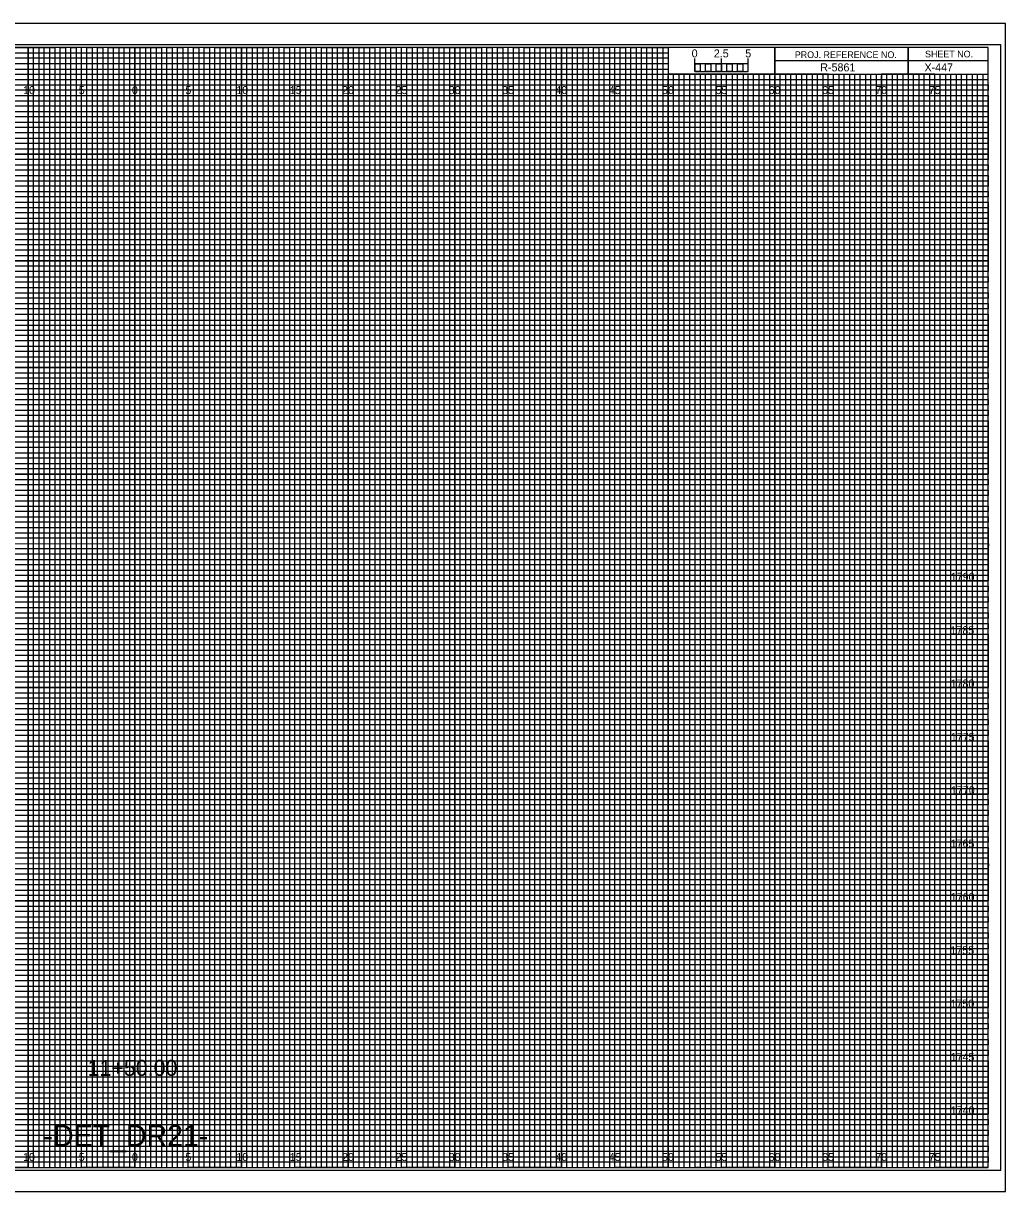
# Model space of a CAD drawing. Extents: x -7 to 162, y -2 to 217.
# Drawn here: x 69.5 to 161.7, y 107.7 to 217.2 of the extents above; entities that cross this region are included whole.
import ezdxf

# ---------------------------------------------------------------- set-up
doc = ezdxf.new("R2010")
doc.units = 0
for name, color, linetype in [('Prop Horizontal Alignment', 7, 'Continuous'), ('Prop XS Alignment Label', 7, 'Continuous'), ('Prop XS Bar Scale Labels', 7, 'Continuous'), ('Prop XS Project Number', 7, 'Continuous'), ('Prop XS Sheet Number', 7, 'Continuous'), ('Raster_Level_0', 7, 'Continuous'), ('Scratch_Level_3', 7, 'Continuous'), ('Sheet Cross Section CELL', 7, 'Continuous'), ('Sheet Cross Section Grid Major CELL', 7, 'Continuous'), ('Sheet Cross Section Grid Middle CELL', 7, 'Continuous'), ('Sheet Cross Section Grid Minor 1 CELL', 7, 'Continuous'), ('Sheet Cross Section Grid Minor 2 CELL', 7, 'Continuous'), ('Sheet Cross Section Scale CELL', 7, 'Continuous'), ('Sheet Cutting Line CELL', 7, 'Continuous'), ('Sheet DOT Grid CELL', 7, 'Continuous'), ('Sheet Plot Border Inside CELL', 7, 'Continuous'), ('Sheet Plot Border Outside CELL', 7, 'Continuous')]:
    doc.layers.add(name, color=color, linetype=linetype)

msp = doc.modelspace()

# ---------------------------------------------------------------- linework, layer by layer
at = {"layer": 'Sheet Cross Section CELL'}
for p, q in [((152.5, 215), (152.5, 212.5)), ((152.5, 212.5), (152.5, 215)), ((160, 213.75), (140, 213.75)), ((140, 213.75), (140, 212.5)), ((140, 212.5), (160, 212.5))]:
    msp.add_line(p, q, dxfattribs=at)
for points in [[(160, 215), (0, 215), (0, 110), (160, 110)], [(140, 215), (130, 215), (130, 212.52), (140, 212.52)], [(160, 215), (140, 215), (140, 212.5), (160, 212.5)]]:
    msp.add_lwpolyline(points, close=True, dxfattribs=at)
at = {"layer": 'Sheet Cross Section Grid Major CELL'}
for p, q in [((75, 215), (70, 215)), ((70, 215), (70, 110)), ((75, 110), (75, 215)), ((85, 215), (80, 215)), ((80, 215), (80, 110)), ((85, 110), (85, 215)), ((95, 215), (90, 215)), ((90, 215), (90, 110)), ((95, 110), (95, 215)), ((105, 215), (100, 215)), ((100, 215), (100, 110)), ((105, 110), (105, 215)), ((115, 215), (110, 215)), ((110, 215), (110, 110)), ((115, 110), (115, 215)), ((125, 215), (120, 215)), ((120, 215), (120, 110)), ((125, 110), (125, 215)), ((130, 215), (130, 110)), ((135, 110), (135, 212.5)), ((145, 212.5), (140, 212.5)), ((140, 212.5), (140, 110)), ((145, 110), (145, 212.5)), ((155, 212.5), (150, 212.5)), ((150, 212.5), (150, 110)), ((155, 110), (155, 212.5)), ((70, 110), (65, 110)), ((80, 110), (75, 110)), ((90, 110), (85, 110)), ((100, 110), (95, 110)), ((110, 110), (105, 110)), ((120, 110), (115, 110)), ((130, 110), (125, 110)), ((140, 110), (135, 110)), ((150, 110), (145, 110)), ((160, 110), (155, 110)), ((160, 110), (160, 110))]:
    msp.add_line(p, q, dxfattribs=at)
for points in [[(0, 210), (160, 210), (160, 205), (0, 205)], [(0, 200), (160, 200), (160, 195), (0, 195)], [(0, 190), (160, 190), (160, 185), (0, 185)], [(0, 180), (160, 180), (160, 175), (0, 175)], [(0, 170), (160, 170), (160, 165), (0, 165)], [(0, 160), (160, 160), (160, 155), (0, 155)], [(0, 150), (160, 150), (160, 145), (0, 145)], [(0, 140), (160, 140), (160, 135), (0, 135)], [(0, 130), (160, 130), (160, 125), (0, 125)], [(0, 120), (160, 120), (160, 115), (0, 115)]]:
    msp.add_lwpolyline(points, dxfattribs=at)
at = {"layer": 'Sheet Cross Section Grid Middle CELL'}
for points in [[(67.5, 215), (72.5, 215), (72.5, 110), (77.5, 110), (77.5, 215), (82.5, 215), (82.5, 110), (87.5, 110), (87.5, 215), (92.5, 215), (92.5, 110), (97.5, 110), (97.5, 215), (102.5, 215), (102.5, 110), (107.5, 110), (107.5, 215), (112.5, 215), (112.5, 110), (117.5, 110), (117.5, 215), (122.5, 215), (122.5, 110), (127.5, 110), (127.5, 215), (129.97, 215), (130, 215), (130, 212.5), (132.5, 212.5), (132.5, 110), (137.5, 110), (137.5, 212.5), (142.5, 212.5), (142.5, 110), (147.5, 110), (147.5, 212.5), (152.5, 212.5), (152.5, 110), (157.5, 110), (157.5, 212.5)], [(0, 212.5), (137.5, 212.5)], [(0, 202.5), (160, 202.5), (160, 207.5), (0, 207.5)], [(0, 192.5), (160, 192.5), (160, 197.5), (0, 197.5)], [(0, 182.5), (160, 182.5), (160, 187.5), (0, 187.5)], [(0, 172.5), (160, 172.5), (160, 177.5), (0, 177.5)], [(0, 162.5), (160, 162.5), (160, 167.5), (0, 167.5)], [(0, 152.5), (160, 152.5), (160, 157.5), (0, 157.5)], [(0, 142.5), (160, 142.5), (160, 147.5), (0, 147.5)], [(0, 132.5), (160, 132.5), (160, 137.5), (0, 137.5)], [(0, 122.5), (160, 122.5), (160, 127.5), (0, 127.5)], [(0, 112.5), (160, 112.5), (160, 117.5), (0, 117.5)]]:
    msp.add_lwpolyline(points, dxfattribs=at)
at = {"layer": 'Sheet Cross Section Grid Minor 1 CELL'}
for p, q in [((0, 214.5), (130, 214.5)), ((130, 213.99), (0, 213.99)), ((130, 214.5), (130, 213.99)), ((0, 213.5), (130, 213.5)), ((130, 212.94), (0, 212.94)), ((130, 213.5), (130, 212.94)), ((0, 212), (160, 212))]:
    msp.add_line(p, q, dxfattribs=at)
for points in [[(0, 211.5), (135, 211.5), (160, 211.5), (160, 211), (0, 211)], [(0, 210.5), (160, 210.5), (160, 209.5), (0, 209.5)], [(0, 209), (160, 209), (160, 208.5), (0, 208.49)], [(0, 208), (160, 208), (160, 207), (0, 207)], [(0, 206.5), (160, 206.5), (160, 206), (0, 206)], [(0, 205.5), (160, 205.5), (160, 204.5), (0, 204.5)], [(0, 204), (160, 204), (160, 203.5), (0, 203.5)], [(0, 203), (160, 203), (160, 202), (0, 202)], [(0, 201.5), (160, 201.5), (160, 201), (0, 201)], [(0, 200.5), (160, 200.5), (160, 199.5), (0, 199.5)], [(0, 199), (160, 199), (160, 198.5), (0, 198.5)], [(0, 198), (160, 198), (160, 196.97), (160, 196.5), (160, 196), (0, 196)], [(0, 197), (160, 197), (160, 196.5), (0, 196.5)], [(0, 195.5), (160, 195.5), (160, 194.5), (0, 194.52)], [(0, 194.52), (160, 194.5), (160, 194), (0, 194)], [(0, 193.5), (160, 193.5), (160, 193), (0, 193)], [(0, 192), (160, 192), (160, 191.5), (0, 191.5)], [(0, 191), (160, 191), (160, 190.5), (0, 190.5)], [(-0.04, 189.44), (160, 189.44), (160, 188.94), (-0.04, 188.94)], [(0, 188.5), (160, 188.5), (160, 188), (0, 188)], [(0, 187), (160, 187), (160, 186.5), (0, 186.5)], [(0, 186), (160, 186), (160, 185.5), (0, 185.5)], [(0, 184.5), (160, 184.5), (160, 184), (0, 184)], [(0, 183.5), (160, 183.5), (160, 183), (0, 183)], [(0, 182), (160, 182), (160, 181.5), (0, 181.5)], [(0, 181), (160, 181), (160, 180.5), (0, 180.5)], [(0, 179.5), (160, 179.5), (160, 178.99), (0, 179)], [(0, 178.5), (160, 178.5), (160, 178), (0, 178)], [(0, 177), (160, 177), (160, 176.5), (0, 176.5)], [(0, 176), (160, 176), (160, 175.5), (0, 175.5)], [(0, 174.5), (160, 174.5), (160, 174), (0, 174)], [(0, 173.5), (160, 173.5), (160, 173), (0, 173)], [(0, 172), (160, 172), (160, 171.5), (0, 171.5)], [(0, 171), (160, 171), (160, 170.5), (0, 170.5)], [(0, 169.5), (160, 169.5), (160, 169), (0, 169)], [(0, 168.5), (160.03, 168.46), (160, 168), (0, 168)], [(0, 167), (160, 167), (160, 166.5), (0, 166.5)], [(0, 166), (160, 166), (160, 165.5), (0, 165.5)], [(0, 164.5), (160, 164.5), (160, 164), (0, 164)], [(0, 163.5), (160, 163.5), (160, 163), (0, 163)], [(0, 162), (160, 162), (160, 161.5), (0, 161.5)], [(0, 161), (160, 161), (160, 160.5), (0, 160.5)], [(0, 159.5), (160, 159.5), (160, 159), (0, 159)], [(0, 158.5), (160, 158.5), (160, 158), (0, 158)], [(0, 157), (160, 157), (160, 156.5), (0, 156.5)], [(0, 156), (160, 156), (160, 155.5), (0, 155.5)], [(0, 154.5), (160, 154.5), (160, 154), (0, 154)], [(0, 153.5), (160, 153.5), (160, 153), (0, 153)], [(0, 152), (160, 152), (160, 151.5), (0, 151.5)], [(0, 151), (160, 151), (160, 150.5), (0, 150.5)], [(0, 149.5), (160, 149.5), (160, 148.99), (0, 149)], [(0, 148.5), (160, 148.5), (160, 148), (0, 148)], [(0, 147), (160, 147), (160, 146.5), (0, 146.5)], [(0, 146), (160, 146), (160, 145.5), (0, 145.5)], [(0, 144.5), (160, 144.5), (160, 144), (0, 144)], [(0, 143.5), (160, 143.5), (160, 143), (0, 143)], [(0, 142), (160, 142), (160, 141.5), (0, 141.5)], [(0, 141), (160, 141), (160, 140.5), (0, 140.5)], [(0, 139.5), (160, 139.5), (160, 139), (0, 139)], [(0, 138.5), (160.03, 138.46), (160, 138), (0, 138)], [(0, 137), (160, 137), (160, 136.5), (0, 136.5)], [(0, 136), (160, 136), (160, 135.5), (0, 135.5)], [(0, 134.5), (160, 134.5), (160, 134), (0, 134)], [(0, 133.5), (160, 133.5), (160, 133), (0, 133)], [(0, 132), (160, 132), (160, 131.5), (0, 131.5)], [(0, 131), (160, 131), (160, 130.5), (0, 130.5)], [(0, 129.5), (160, 129.5), (160, 129), (0, 129)], [(0, 128.5), (160, 128.5), (160, 128), (0, 128)], [(0, 127), (160, 127), (160, 126.5), (0, 126.5)], [(0, 126), (160, 126), (160, 125.5), (0, 125.5)], [(0, 124.5), (160, 124.5), (160, 124), (0, 124)], [(0, 123.5), (160, 123.5), (160, 123), (0, 123)], [(0, 122), (160, 122), (160, 121.5), (0, 121.5)], [(0, 121), (160, 121), (160, 120.5), (0, 120.5)], [(0, 119.5), (160, 119.5), (160, 119), (0, 119)], [(0, 118.5), (160, 118.5), (160, 118), (0, 118)], [(0, 117), (160, 117), (160, 116.5), (0, 116.5)], [(0, 116), (160, 116), (160, 115.5), (0, 115.5)], [(0, 114.5), (160, 114.5), (160, 114), (0, 114)], [(0, 113.5), (160, 113.5), (160, 113), (0, 113)], [(0, 112), (160, 112), (160, 111.5), (0, 111.5)], [(0, 111), (160, 111), (160, 110.5), (0, 110.5)]]:
    msp.add_lwpolyline(points, dxfattribs=at)
at = {"layer": 'Sheet Cross Section Grid Minor 2 CELL'}
for p, q in [((133.5, 212.5), (133, 212.5)), ((133, 212.5), (133, 110)), ((133.5, 110), (133.5, 212.5)), ((134.5, 212.5), (134, 212.5)), ((134, 212.5), (134, 110)), ((134.5, 110), (134.5, 212.5)), ((133, 110), (132.5, 110)), ((134, 110), (133.5, 110))]:
    msp.add_line(p, q, dxfattribs=at)
for points in [[(70, 110), (70.5, 110), (70.5, 215), (71, 215), (71, 110)], [(71, 110), (71.5, 110), (71.5, 215), (72, 215), (72, 110)], [(72.5, 110), (73, 110), (73, 215), (73.5, 215), (73.5, 110)], [(73.5, 110), (74, 110), (74, 215), (74.5, 215), (74.5, 110)], [(75, 110), (75.5, 110), (75.5, 215), (76, 215), (76, 110)], [(76, 110), (76.5, 110), (76.5, 215), (77, 215), (77, 110)], [(77.5, 110), (78, 110), (78, 215), (78.5, 215), (78.5, 110)], [(78.5, 110), (79, 110), (79, 215), (79.5, 215), (79.5, 110)], [(80, 110), (80.5, 110), (80.5, 215), (81, 215), (81, 110)], [(81, 110), (81.5, 110), (81.5, 215), (82, 215), (82, 110)], [(82.5, 110), (83, 110), (83, 215), (83.5, 215), (83.5, 110)], [(83.5, 110), (84, 110), (84, 215), (84.5, 215), (84.5, 110)], [(85, 110), (85.5, 110), (85.5, 215), (86, 215), (86, 110)], [(86, 110), (86.5, 110), (86.5, 215), (87, 215), (87, 110)], [(87.5, 110), (88, 110), (88, 215), (88.5, 215), (88.5, 110)], [(88.5, 110), (89, 110), (89, 215), (89.5, 215), (89.5, 110)], [(90, 110), (90.5, 110), (90.5, 215), (91, 215), (91, 110)], [(91, 110), (91.5, 110), (91.5, 215), (92, 215), (92, 110)], [(92.5, 110), (93, 110), (93, 215), (93.5, 215), (93.5, 110)], [(93.5, 110), (94, 110), (94, 215), (94.5, 215), (94.5, 110)], [(95, 110), (95.5, 110), (95.5, 215), (96, 215), (96, 110)], [(96, 110), (96.5, 110), (96.5, 215), (97, 215), (97, 110)], [(97.5, 110), (98, 110), (98, 215), (98.5, 215), (98.5, 110)], [(98.5, 110), (99, 110), (99, 215), (99.5, 215), (99.5, 110)], [(100, 110), (100.5, 110), (100.5, 215), (101, 215), (101, 110)], [(101, 110), (101.5, 110), (101.5, 215), (102, 215), (102, 110)], [(102.5, 110), (103, 110), (103, 215), (103.5, 215), (103.5, 110)], [(103.5, 110), (104, 110), (104, 215), (104.5, 215), (104.5, 110)], [(105, 110), (105.5, 110), (105.5, 215), (106, 215), (106, 110)], [(106, 110), (106.5, 110), (106.5, 215), (107, 215), (107, 110)], [(107.5, 110), (108, 110), (108, 215), (108.5, 215), (108.5, 110)], [(108.5, 110), (109, 110), (109, 215), (109.5, 215), (109.5, 110)], [(110, 110), (110.5, 110), (110.5, 215), (111, 215), (111, 110)], [(111, 110), (111.5, 110), (111.5, 215), (112, 215), (112, 110)], [(112.5, 110), (113, 110), (113, 215), (113.5, 215), (113.5, 110)], [(113.5, 110), (114, 110), (114, 215), (114.5, 215), (114.5, 110)], [(115, 110), (115.5, 110), (115.5, 215), (116, 215), (116, 110)], [(116, 110), (116.5, 110), (116.5, 215), (117, 215), (117, 110)], [(117.5, 110), (118, 110), (118, 215), (118.5, 215), (118.5, 110)], [(118.5, 110), (119, 110), (119, 215), (119.5, 215), (119.5, 110)], [(120, 110), (120.5, 110), (120.5, 215), (121, 215), (121, 110)], [(121, 110), (121.5, 110), (121.5, 215), (122, 215), (122, 110)], [(122.5, 110), (123, 110), (123, 215), (123.5, 215), (123.5, 110)], [(123.5, 110), (124, 110), (124, 215), (124.5, 215), (124.5, 110)], [(125, 110), (125.5, 110), (125.5, 215), (126, 215), (126, 110)], [(126, 110), (126.5, 110), (126.5, 215), (127, 215), (127, 110)], [(127.5, 110), (128, 110), (128, 215), (128.5, 215), (128.5, 110)], [(128.5, 110), (129, 110), (129, 215), (129.5, 215), (129.5, 110)], [(130, 110), (130.5, 110), (130.5, 212.5), (131.01, 212.5), (131.01, 110)], [(131, 110), (131.5, 110), (131.5, 212.5), (132, 212.5), (132, 110)], [(135, 110), (135.49, 110), (135.49, 212.5), (136, 212.5), (136, 110)], [(136, 110), (136.5, 110), (136.5, 212.5), (137.03, 212.5), (137.03, 110)], [(137.5, 110), (138, 110), (138, 212.5), (138.5, 212.5), (138.5, 110)], [(138.5, 110), (139, 110), (139, 212.5), (139.5, 212.5), (139.5, 110)], [(140, 110), (140.5, 110), (140.5, 212.5), (141, 212.5), (141, 110)], [(141, 110), (141.5, 110), (141.5, 212.5), (142, 212.5), (142, 110)], [(142.5, 110), (143, 110), (143, 212.5), (143.5, 212.5), (143.5, 110)], [(143.5, 110), (144, 110), (144, 212.5), (144.5, 212.5), (144.5, 110)], [(145, 110), (145.5, 110), (145.5, 212.5), (146, 212.5), (146, 110)], [(146, 110), (146.5, 110), (146.5, 212.5), (147, 212.5), (147, 110)], [(147.5, 110), (148, 110), (148, 212.5), (148.5, 212.5), (148.5, 110)], [(148.5, 110), (149, 110), (149, 212.5), (149.5, 212.5), (149.5, 110)], [(150, 110), (150.5, 110), (150.5, 212.5), (151, 212.5), (151, 110)], [(151, 110), (151.5, 110), (151.5, 212.5), (152, 212.5), (152, 110)], [(152.5, 110), (153, 110), (153, 212.5), (153.5, 212.5), (153.5, 110)], [(153.5, 110), (154, 110), (154, 212.5), (154.5, 212.5), (154.5, 110)], [(155, 110), (155.5, 110), (155.5, 212.5), (156, 212.5), (156, 110)], [(156, 110), (156.5, 110), (156.5, 212.5), (157, 212.5), (157, 110)], [(157.5, 110), (158, 110), (158, 212.5), (158.5, 212.5), (158.5, 110)], [(158.5, 110), (159, 110), (159, 212.5), (159.5, 212.5), (159.5, 110)]]:
    msp.add_lwpolyline(points, dxfattribs=at)
at = {"layer": 'Sheet Cross Section Scale CELL'}
for p, q in [((132.5, 212.75), (132.5, 213.95)), ((132.5, 213.45), (132.5, 213.95)), ((135, 212.75), (135, 213.95)), ((137.5, 212.75), (137.5, 213.95)), ((137.5, 213.45), (137.5, 213.95))]:
    msp.add_line(p, q, dxfattribs=at)
for points in [[(137.5, 213.45), (132.5, 213.45), (132.5, 212.75), (137.5, 212.75)], [(132.5, 213.45), (133, 213.45), (133, 212.75), (132.5, 212.75)], [(133.5, 213.45), (134, 213.45), (134, 212.75), (133.5, 212.75)], [(134.5, 213.45), (135, 213.45), (135, 212.75), (134.5, 212.75)], [(135.5, 213.45), (136, 213.45), (136, 212.75), (135.5, 212.75)], [(136.5, 213.45), (137, 213.45), (137, 212.75), (136.5, 212.75)]]:
    msp.add_lwpolyline(points, close=True, dxfattribs=at)
at = {"layer": 'Sheet Cutting Line CELL'}
for p, q in [((161.65, 217.25), (-6.7, 217.25)), ((-6.7, 107.75), (161.65, 107.75))]:
    msp.add_line(p, q, dxfattribs=at)
at = {"layer": 'Sheet DOT Grid CELL'}
for p, q in [((70, 110), (70, 215)), ((75, 110), (75, 215)), ((80, 110), (80, 215)), ((85, 110), (85, 215)), ((90, 110), (90, 215)), ((95, 110), (95, 215)), ((100, 110), (100, 215)), ((105, 110), (105, 215)), ((110, 110), (110, 215)), ((115, 110), (115, 215)), ((120, 110), (120, 215)), ((125, 110), (125, 215)), ((130, 110), (130, 212.34)), ((135, 110), (135, 212.34)), ((140, 110), (140, 212.34)), ((145, 110), (145, 212.34)), ((150, 110), (150, 212.34)), ((155, 110), (155, 212.34)), ((0, 210), (160, 210)), ((0, 205), (160, 205)), ((0, 200), (160, 200)), ((0, 195), (160, 195)), ((0, 190), (160, 190)), ((0, 185), (160, 185)), ((0, 180), (160, 180)), ((0, 175), (160, 175)), ((0, 170), (160, 170)), ((0, 165), (160, 165)), ((0, 160), (160, 160)), ((0, 155), (160, 155)), ((0, 150), (160, 150)), ((0, 145), (160, 145)), ((0, 140), (160, 140)), ((0, 135), (160, 135)), ((0, 130), (160, 130)), ((0, 125), (160, 125)), ((0, 120), (160, 120)), ((0, 115), (160, 115))]:
    msp.add_line(p, q, dxfattribs=at)
at = {"layer": 'Sheet Plot Border Inside CELL'}
msp.add_lwpolyline([(-5.4, 109.75), (161.2, 109.75), (161.2, 215.25), (-5.4, 215.25)], close=True, dxfattribs=at)
at = {"layer": 'Sheet Plot Border Outside CELL'}
msp.add_lwpolyline([(-6.7, 107.75), (161.65, 107.75), (161.65, 217.25), (-6.7, 217.25)], close=True, dxfattribs=at)

# ---------------------------------------------------------------- texts
at = {"layer": 'Prop Horizontal Alignment'}
msp.add_text('11+50.00', height=1.5, dxfattribs=at).set_placement((75.57, 118.6))
at = {"layer": 'Prop XS Alignment Label'}
msp.add_text('-DET_DR21-', height=2, dxfattribs=at).set_placement((71.44, 112))
at = {"layer": 'Prop XS Bar Scale Labels'}
for s, p in [('2.5', (134.29, 214.06)), ('5', (137.24, 214.06))]:
    msp.add_text(s, height=0.75, dxfattribs=at).set_placement(p)
at = {"layer": 'Prop XS Project Number'}
msp.add_text('R-5861', height=0.75, dxfattribs=at).set_placement((144.27, 212.75))
at = {"layer": 'Prop XS Sheet Number'}
msp.add_text('X-447', height=0.75, dxfattribs=at).set_placement((154.04, 212.75))
at = {"layer": 'Raster_Level_0'}
for s, p in [('10', (69.52, 210.62)), ('5', (74.74, 210.62)), ('0', (79.73, 210.62)), ('0', (79.73, 210.62)), ('5', (84.74, 210.62)), ('10', (89.52, 210.62)), ('15', (94.53, 210.62)), ('20', (99.43, 210.62)), ('25', (104.44, 210.62)), ('30', (109.43, 210.62)), ('35', (114.44, 210.62)), ('40', (119.43, 210.62)), ('45', (124.44, 210.62)), ('50', (129.43, 210.62)), ('55', (134.44, 210.62)), ('60', (139.43, 210.62)), ('65', (144.44, 210.62)), ('70', (149.43, 210.62)), ('75', (154.44, 210.62)), ('10', (69.52, 110.62)), ('5', (74.74, 110.62)), ('0', (79.73, 110.62)), ('0', (79.73, 110.62)), ('5', (84.74, 110.62)), ('10', (89.52, 110.62)), ('15', (94.53, 110.62)), ('20', (99.43, 110.62)), ('25', (104.44, 110.62)), ('30', (109.43, 110.62)), ('35', (114.44, 110.62)), ('40', (119.43, 110.62)), ('45', (124.44, 110.62)), ('50', (129.43, 110.62)), ('55', (134.44, 110.62)), ('60', (139.43, 110.62)), ('65', (144.44, 110.62)), ('70', (149.43, 110.62)), ('75', (154.44, 110.62))]:
    msp.add_text(s, height=0.75, dxfattribs=at).set_placement(p)
at = {"layer": 'Scratch_Level_3'}
for s, p in [('1790', (156.5, 165)), ('1785', (156.48, 160)), ('1780', (156.49, 155)), ('1775', (156.51, 150)), ('1770', (156.52, 145)), ('1765', (156.49, 140)), ('1760', (156.5, 135)), ('1755', (156.47, 130)), ('1750', (156.48, 125)), ('1745', (156.49, 120)), ('1740', (156.5, 115))]:
    msp.add_text(s, height=0.75, dxfattribs=at).set_placement(p)
at = {"layer": 'Sheet Cross Section CELL'}
for s, p in [('PROJ. REFERENCE NO.', (141.88, 214)), ('SHEET NO.', (154.09, 214.06))]:
    msp.add_text(s, height=0.625, dxfattribs=at).set_placement(p)
at = {"layer": 'Sheet Cross Section Scale CELL'}
msp.add_text('0', height=0.75, dxfattribs=at).set_placement((132.21, 214.06))

doc.saveas('drawing.dxf')
